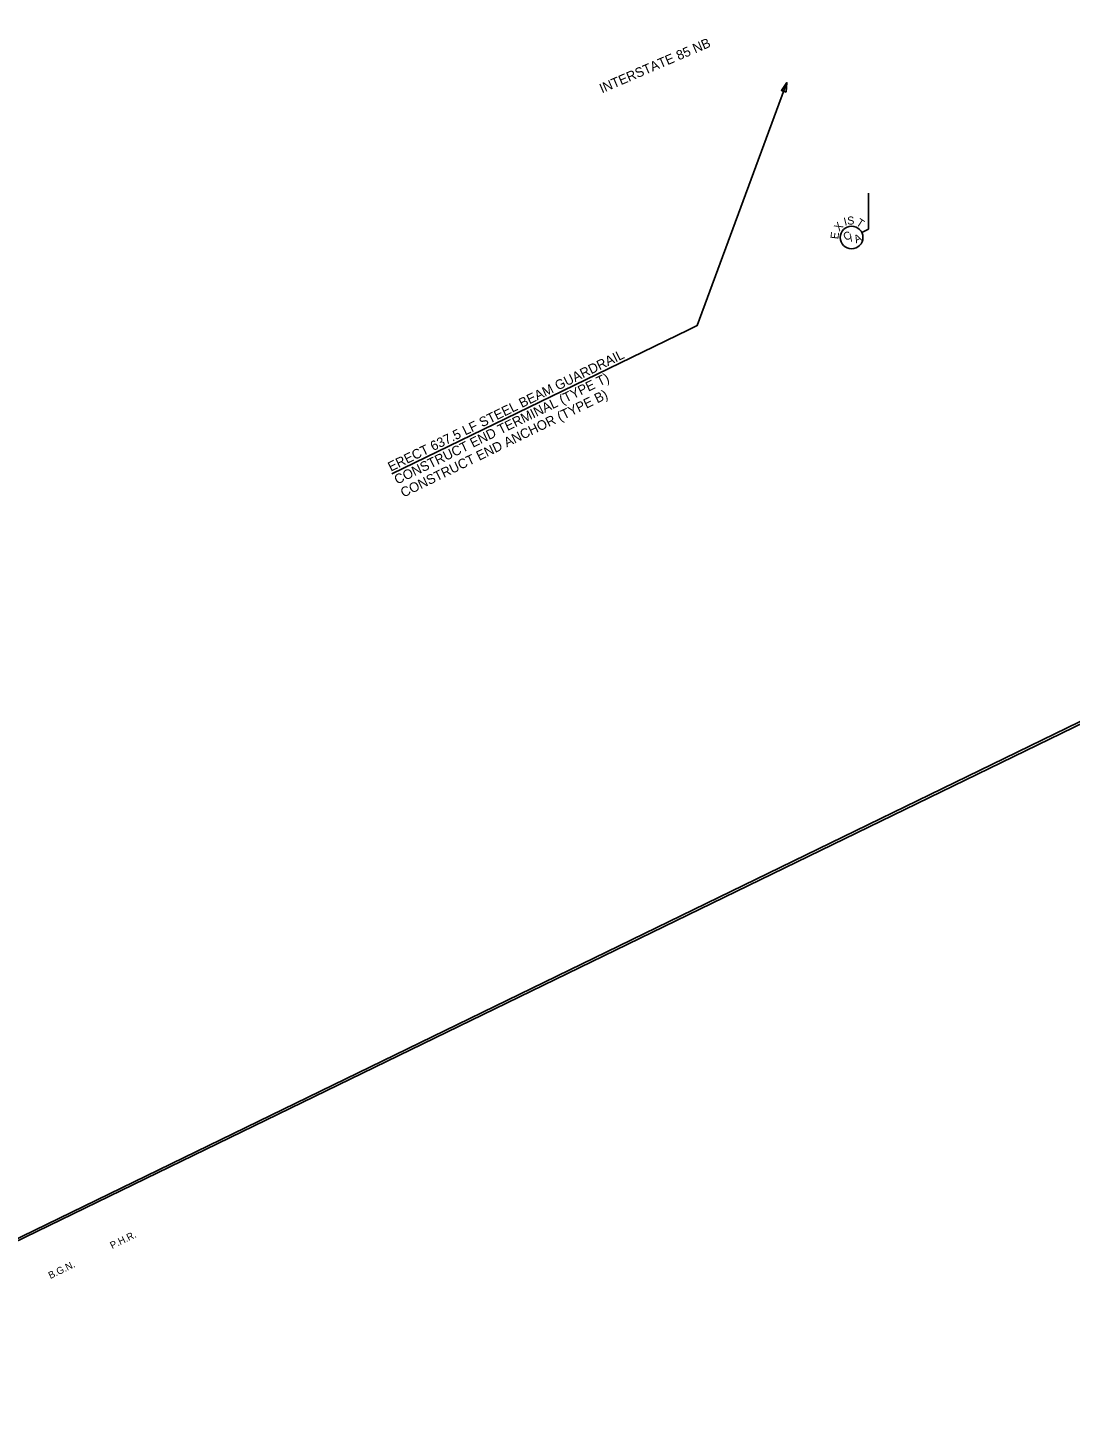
# Model space of a CAD drawing. Extents: x 1616869 to 1620470, y 1100482 to 1103335.
# Drawn here: x 1617500 to 1618151, y 1100504 to 1101363 of the extents above; entities that cross this region are included whole.
import ezdxf

# ---------------------------------------------------------------- set-up
doc = ezdxf.new("R2010")
doc.units = 0
for name, color, linetype in [('Level 2', 7, 'Continuous'), ('Level 4', 7, 'Continuous'), ('Level 44', 7, 'Continuous'), ('RD_EX_Control_Access', 7, 'Continuous'), ('RD_PD_DR_Pipe', 7, 'Continuous'), ('RD_SHT_TX', 7, 'Continuous')]:
    doc.layers.add(name, color=color, linetype=linetype)

msp = doc.modelspace()

# ---------------------------------------------------------------- linework, layer by layer
at = {"layer": 'Level 2'}
msp.add_lwpolyline([(1616868.78, 1101364.63), (1618375.15, 1102097.07), (1618793.41, 1101236.86), (1617287.04, 1100504.42)], close=True, dxfattribs=at)
at = {"layer": 'Level 4'}
msp.add_lwpolyline([(1617080.14, 1101099.03), (1617256.2, 1100856.12), (1617395.1, 1100558.35), (1618700.82, 1101193.66), (1618573.12, 1101494.1), (1618454.8, 1101769.78), (1618339.83, 1102037.66), (1618182.95, 1101960.1), (1618167.86, 1101990.6), (1616961.35, 1101407.95), (1616972.59, 1101384.68), (1616914.03, 1101356.41)], close=True, dxfattribs=at)
msp.add_lwpolyline([(1617080.14, 1101099.03), (1617256.2, 1100856.12), (1617395.1, 1100558.35), (1618700.82, 1101193.66), (1618573.12, 1101494.1), (1618454.8, 1101769.78), (1618339.83, 1102037.66), (1618182.95, 1101960.1), (1618167.86, 1101990.6), (1616961.35, 1101407.95), (1616972.59, 1101384.68), (1616914.03, 1101356.41)], close=True, dxfattribs=at)
at = {"layer": 'Level 44'}
msp.add_line((1617912.63, 1101174), (1617727.47, 1101083.97), dxfattribs=at)
msp.add_lwpolyline([(1617912.63, 1101174), (1617918.08, 1101176.65), (1617974.19, 1101328.48)], dxfattribs=at)
msp.add_lwpolyline([(1617973.63, 1101322.51), (1617974.19, 1101328.48), (1617970.72, 1101323.58)], close=True, dxfattribs=at)
at = {"layer": 'RD_PD_DR_Pipe'}
for p, q in [((1618025.08, 1101236.8), (1618025.24, 1101259.39)), ((1618020.97, 1101234.8), (1618025.08, 1101236.8))]:
    msp.add_line(p, q, dxfattribs=at)
msp.add_circle((1618014.6, 1101231.7), 7.08, dxfattribs=at)

# ---------------------------------------------------------------- texts
at = {"layer": 'Level 44'}
for s, p in [('ERECT 637.5 LF STEEL BEAM GUARDRAIL', (1617726.81, 1101085.31)), ('CONSTRUCT END TERMINAL (TYPE T)', (1617730.75, 1101077.22)), ('CONSTRUCT END ANCHOR (TYPE B)', (1617734.68, 1101069.13))]:
    msp.add_text(s, height=6, rotation=25.93046, dxfattribs=at).set_placement(p)
at = {"layer": 'RD_EX_Control_Access'}
msp.add_text('INTERSTATE 85 NB', height=6, rotation=23.22168, dxfattribs=at).set_placement((1617858.7, 1101321.69))
at = {"layer": 'RD_PD_DR_Pipe'}
for s, rotation, p in [('X', 49.07183, (1618006.94, 1101235.21)), ('I', 13.91036, (1618010.36, 1101238.97)), ('S', 2.18987, (1618011.93, 1101239.68)), ('T', 327.02839, (1618017.01, 1101239.76)), ('E', 82.55895, (1618006.27, 1101230.4)), ('C', 25.92721, (1618010.85, 1101229.44)), ('/', 25.92721, (1618014.43, 1101228.84)), ('A', 25.92721, (1618017.47, 1101227.92))]:
    msp.add_text(s, height=5, rotation=rotation, dxfattribs=at).set_placement(p)
at = {"layer": 'RD_SHT_TX'}
for s, p in [('P.H.R.', (1617552.74, 1100599.67)), ('B.G.N.', (1617514.19, 1100580.92))]:
    msp.add_text(s, height=4.4, rotation=25.93046, dxfattribs=at).set_placement(p)

doc.saveas('drawing.dxf')
